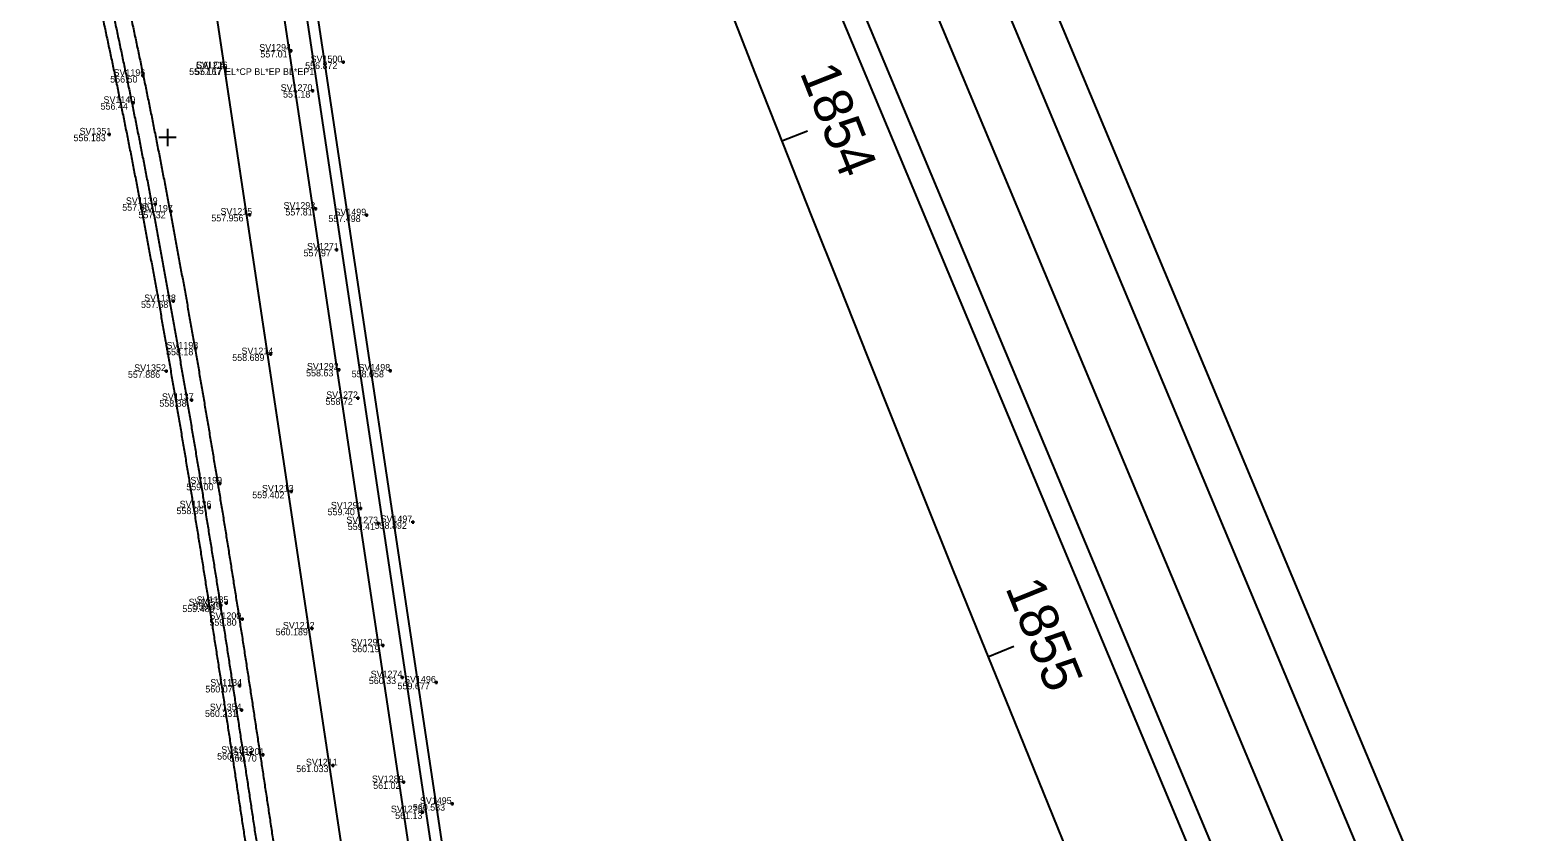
# Model space of a CAD drawing. Extents: x 6334 to 41599, y 9030 to 59113.
# Drawn here: x 21027.9 to 21299.4, y 34615.6 to 34759.9 of the extents above; entities that cross this region are included whole.
import ezdxf

# ---------------------------------------------------------------- set-up
doc = ezdxf.new("R2010")
doc.units = 0
for name, color, linetype in [('GE_X_CL_20', 7, 'Continuous'), ('GE_X_CL_50', 7, 'Continuous'), ('GK_Visualization', 7, 'Continuous'), ('PM_X_CL_Double_Solid', 7, 'Continuous'), ('PM_X_Lane_Line', 7, 'Continuous'), ('PV_X_EOP', 7, 'Continuous'), ('PV_X_Shoulder', 7, 'Continuous'), ('RD_X_GR_Lt', 7, 'Continuous'), ('RD_X_GR_Rt', 7, 'Continuous'), ('SV_X_Shot_Marker', 7, 'Continuous'), ('SV_X_Text_Comment', 7, 'Continuous'), ('SV_X_Text_Elevation', 7, 'Continuous'), ('SV_X_Text_Name', 7, 'Continuous')]:
    doc.layers.add(name, color=color, linetype=linetype)

msp = doc.modelspace()

# ---------------------------------------------------------------- linework, layer by layer
at = {"layer": 'GE_X_CL_20'}
msp.add_arc((24529.94, 36271.9), 3906.53, 186.21667, 209.21667, dxfattribs=at)
at = {"layer": 'GE_X_CL_50'}
for p, q in [((21163.23, 34739.98), (21167.88, 34741.81)), ((21200.36, 34647.12), (21205, 34649))]:
    msp.add_line(p, q, dxfattribs=at)
msp.add_arc((32581.78, 39251.96), 12277.67, 194.525, 202.716667, dxfattribs=at)
at = {"layer": 'GK_Visualization'}
for p, q in [((21051.3, 34829.99), (21084.27, 34610.45)), ((21051.3, 34829.99), (21084.27, 34610.45)), ((21182.19, 34784.02), (22003.54, 32822.13)), ((21054.16, 34740.61), (21051.04, 34740.61)), ((21052.6, 34742.17), (21052.6, 34739.05))]:
    msp.add_line(p, q, dxfattribs=at)
for centre, radius, start, end in [((32581.78, 39251.96), 12277.67, 194.525, 202.716667), ((32581.78, 39251.96), 12277.67, 194.525, 202.716667), ((24529.91, 36271.94), 3906.53, 186.21497, 209.2138), ((24529.91, 36271.94), 3906.53, 186.21497, 209.2138), ((24529.94, 36271.9), 3906.53, 186.21667, 209.21667), ((24529.94, 36271.9), 3906.53, 186.21667, 209.21667)]:
    msp.add_arc(centre, radius, start, end, dxfattribs=at)
msp.add_spline([(21035.84, 34805.21), (21036.52, 34802.59), (21037.19, 34799.97), (21037.85, 34797.35), (21038.5, 34794.73), (21039.15, 34792.11), (21039.79, 34789.48), (21040.42, 34786.85), (21041.04, 34784.22), (21041.66, 34781.59), (21042.28, 34778.96), (21042.88, 34776.33), (21043.48, 34773.69), (21044.08, 34771.05), (21044.66, 34768.42), (21045.24, 34765.78), (21045.82, 34763.13), (21046.39, 34760.49), (21046.95, 34757.85), (21047.51, 34755.21), (21048.06, 34752.56), (21048.61, 34749.91), (21049.15, 34747.26), (21049.69, 34744.62), (21050.22, 34741.97), (21050.75, 34739.31), (21051.27, 34736.66), (21051.78, 34734.01), (21052.29, 34731.36), (21052.8, 34728.7), (21053.3, 34726.05), (21053.8, 34723.39), (21054.3, 34720.73), (21054.78, 34718.07), (21055.27, 34715.42), (21055.75, 34712.76), (21056.23, 34710.1), (21056.7, 34707.43), (21057.17, 34704.77), (21057.64, 34702.11), (21058.1, 34699.45), (21058.56, 34696.78), (21059.01, 34694.12), (21059.46, 34691.46), (21059.91, 34688.79), (21060.36, 34686.12), (21060.8, 34683.46), (21061.24, 34680.79), (21061.68, 34678.12), (21062.11, 34675.46), (21062.55, 34672.79), (21062.98, 34670.12), (21063.4, 34667.45), (21063.83, 34664.78), (21064.25, 34662.11), (21064.67, 34659.44), (21065.09, 34656.77), (21065.51, 34654.1), (21065.92, 34651.43), (21066.34, 34648.76), (21066.75, 34646.09), (21067.16, 34643.42), (21067.57, 34640.75), (21067.98, 34638.08), (21068.38, 34635.4), (21068.79, 34632.73), (21069.2, 34630.06), (21069.6, 34627.39), (21070, 34624.72), (21070.41, 34622.04), (21070.81, 34619.37), (21071.21, 34616.7), (21071.61, 34614.03), (21072.01, 34611.35), (21072.42, 34608.68)], degree=3, dxfattribs=at)
at = {"layer": 'PM_X_CL_Double_Solid'}
msp.add_line((21061.45, 34762.43), (21084.27, 34610.45), dxfattribs=at)
at = {"layer": 'PM_X_Lane_Line'}
msp.add_line((21182.19, 34784.02), (22003.54, 32822.13), dxfattribs=at)
for start in [186.21667, 191.33607]:
    msp.add_arc((24529.94, 36271.9), 3906.53, start, 209.21667, dxfattribs=at)
at = {"layer": 'PV_X_EOP'}
for p, q in [((21063.16, 34831.77), (21096.14, 34612.23)), ((21193.26, 34788.66), (22014.61, 32826.77)), ((21171.12, 34779.39), (21992.47, 32817.5))]:
    msp.add_line(p, q, dxfattribs=at)
for centre, radius, start, end in [((24529.94, 36271.9), 3918.53, 191.33607, 209.21667), ((24531.79, 36272.61), 3896.49, 192.87045, 209.21252)]:
    msp.add_arc(centre, radius, start, end, dxfattribs=at)
msp.add_spline([(21035.84, 34805.21), (21036.52, 34802.59), (21037.19, 34799.97), (21037.85, 34797.35), (21038.5, 34794.73), (21039.15, 34792.11), (21039.79, 34789.48), (21040.42, 34786.85), (21041.04, 34784.22), (21041.66, 34781.59), (21042.28, 34778.96), (21042.88, 34776.33), (21043.48, 34773.69), (21044.08, 34771.05), (21044.66, 34768.42), (21045.24, 34765.78), (21045.82, 34763.13), (21046.39, 34760.49), (21046.95, 34757.85), (21047.51, 34755.21), (21048.06, 34752.56), (21048.61, 34749.91), (21049.15, 34747.26), (21049.69, 34744.62), (21050.22, 34741.97), (21050.75, 34739.31), (21051.27, 34736.66), (21051.78, 34734.01), (21052.29, 34731.36), (21052.8, 34728.7), (21053.3, 34726.05), (21053.8, 34723.39), (21054.3, 34720.73), (21054.78, 34718.07), (21055.27, 34715.42), (21055.75, 34712.76), (21056.23, 34710.1), (21056.7, 34707.43), (21057.17, 34704.77), (21057.64, 34702.11), (21058.1, 34699.45), (21058.56, 34696.78), (21059.01, 34694.12), (21059.46, 34691.46), (21059.91, 34688.79), (21060.36, 34686.12), (21060.8, 34683.46), (21061.24, 34680.79), (21061.68, 34678.12), (21062.11, 34675.46), (21062.55, 34672.79), (21062.98, 34670.12), (21063.4, 34667.45), (21063.83, 34664.78), (21064.25, 34662.11), (21064.67, 34659.44), (21065.09, 34656.77), (21065.51, 34654.1), (21065.92, 34651.43), (21066.34, 34648.76), (21066.75, 34646.09), (21067.16, 34643.42), (21067.57, 34640.75), (21067.98, 34638.08), (21068.38, 34635.4), (21068.79, 34632.73), (21069.2, 34630.06), (21069.6, 34627.39), (21070, 34624.72), (21070.41, 34622.04), (21070.81, 34619.37), (21071.21, 34616.7), (21071.61, 34614.03), (21072.01, 34611.35), (21072.42, 34608.68)], degree=3, dxfattribs=at)
at = {"layer": 'PV_X_Shoulder'}
for p, q in [((21067.12, 34832.37), (21100.09, 34612.83)), ((21200.64, 34791.75), (22021.99, 32829.86)), ((21167.43, 34777.85), (21988.78, 32815.95))]:
    msp.add_line(p, q, dxfattribs=at)
for radius, start in [(3926.53, 191.34141), (3890.53, 192.86631)]:
    msp.add_arc((24529.94, 36271.9), radius, start, 209.21667, dxfattribs=at)
msp.add_spline([(21032.94, 34804.46), (21033.61, 34801.85), (21034.28, 34799.24), (21034.94, 34796.62), (21035.59, 34794.01), (21036.23, 34791.39), (21036.87, 34788.77), (21037.5, 34786.15), (21038.12, 34783.53), (21038.74, 34780.91), (21039.35, 34778.28), (21039.96, 34775.66), (21040.56, 34773.03), (21041.15, 34770.4), (21041.73, 34767.77), (21042.31, 34765.13), (21042.89, 34762.5), (21043.46, 34759.86), (21044.02, 34757.23), (21044.57, 34754.59), (21045.13, 34751.95), (21045.67, 34749.31), (21046.21, 34746.67), (21046.75, 34744.02), (21047.28, 34741.38), (21047.8, 34738.73), (21048.32, 34736.09), (21048.84, 34733.44), (21049.35, 34730.79), (21049.85, 34728.14), (21050.36, 34725.49), (21050.85, 34722.84), (21051.35, 34720.19), (21051.83, 34717.53), (21052.32, 34714.88), (21052.8, 34712.22), (21053.27, 34709.57), (21053.75, 34706.91), (21054.22, 34704.25), (21054.68, 34701.6), (21055.14, 34698.94), (21055.6, 34696.28), (21056.05, 34693.62), (21056.51, 34690.96), (21056.95, 34688.29), (21057.4, 34685.63), (21057.84, 34682.97), (21058.28, 34680.3), (21058.72, 34677.64), (21059.15, 34674.98), (21059.58, 34672.31), (21060.01, 34669.65), (21060.44, 34666.98), (21060.87, 34664.31), (21061.29, 34661.65), (21061.71, 34658.98), (21062.13, 34656.31), (21062.54, 34653.64), (21062.96, 34650.97), (21063.37, 34648.3), (21063.78, 34645.63), (21064.19, 34642.96), (21064.6, 34640.29), (21065.01, 34637.62), (21065.42, 34634.95), (21065.82, 34632.28), (21066.23, 34629.61), (21066.63, 34626.94), (21067.04, 34624.27), (21067.44, 34621.6), (21067.84, 34618.92), (21068.24, 34616.25), (21068.65, 34613.58), (21069.05, 34610.91), (21069.45, 34608.23)], degree=3, dxfattribs=at)
at = {"layer": 'RD_X_GR_Lt'}
msp.add_line((21058.92, 34900.43), (21102.07, 34613.12), dxfattribs=at)
at = {"layer": 'RD_X_GR_Rt'}
msp.add_spline([(21031, 34803.96), (21031.68, 34801.35), (21032.34, 34798.74), (21033, 34796.14), (21033.65, 34793.53), (21034.29, 34790.92), (21034.93, 34788.3), (21035.56, 34785.69), (21036.18, 34783.07), (21036.79, 34780.45), (21037.4, 34777.83), (21038.01, 34775.21), (21038.61, 34772.59), (21039.2, 34769.96), (21039.78, 34767.33), (21040.36, 34764.71), (21040.93, 34762.08), (21041.5, 34759.44), (21042.06, 34756.81), (21042.62, 34754.18), (21043.17, 34751.54), (21043.71, 34748.91), (21044.25, 34746.27), (21044.79, 34743.63), (21045.32, 34740.99), (21045.84, 34738.35), (21046.36, 34735.7), (21046.87, 34733.06), (21047.38, 34730.41), (21047.89, 34727.77), (21048.39, 34725.12), (21048.89, 34722.47), (21049.38, 34719.82), (21049.87, 34717.17), (21050.35, 34714.52), (21050.83, 34711.87), (21051.31, 34709.22), (21051.78, 34706.56), (21052.25, 34703.91), (21052.71, 34701.25), (21053.17, 34698.6), (21053.63, 34695.94), (21054.08, 34693.28), (21054.53, 34690.62), (21054.98, 34687.96), (21055.43, 34685.3), (21055.87, 34682.64), (21056.31, 34679.98), (21056.74, 34677.32), (21057.18, 34674.66), (21057.61, 34671.99), (21058.04, 34669.33), (21058.47, 34666.66), (21058.89, 34664), (21059.31, 34661.33), (21059.73, 34658.67), (21060.15, 34656), (21060.57, 34653.33), (21060.98, 34650.67), (21061.4, 34648), (21061.81, 34645.33), (21062.22, 34642.66), (21062.63, 34639.99), (21063.03, 34637.32), (21063.44, 34634.65), (21063.85, 34631.98), (21064.25, 34629.31), (21064.66, 34626.64), (21065.06, 34623.97), (21065.46, 34621.3), (21065.86, 34618.63), (21066.27, 34615.95), (21066.67, 34613.28), (21067.07, 34610.61), (21067.47, 34607.94)], degree=3, dxfattribs=at)
at = {"layer": 'SV_X_Shot_Marker'}
for p, q in [((21075.14, 34756.22), (21074.54, 34756.22)), ((21074.84, 34756.52), (21074.84, 34755.92)), ((21084.56, 34754.15), (21083.96, 34754.15)), ((21084.26, 34754.45), (21084.26, 34753.85)), ((21048.48, 34751.7), (21047.88, 34751.7)), ((21048.18, 34752), (21048.18, 34751.4)), ((21063.27, 34753.07), (21062.67, 34753.07)), ((21063.27, 34753.07), (21062.67, 34753.07)), ((21063.27, 34753.07), (21062.67, 34753.07)), ((21062.97, 34753.37), (21062.97, 34752.77)), ((21062.97, 34753.37), (21062.97, 34752.77)), ((21062.97, 34753.37), (21062.97, 34752.77)), ((21079.02, 34748.99), (21078.42, 34748.99)), ((21078.72, 34749.29), (21078.72, 34748.69)), ((21046.7, 34746.82), (21046.1, 34746.82)), ((21046.4, 34747.12), (21046.4, 34746.52)), ((21042.41, 34741.14), (21041.81, 34741.14)), ((21042.11, 34741.44), (21042.11, 34740.84)), ((21050.69, 34728.62), (21050.09, 34728.62)), ((21050.39, 34728.92), (21050.39, 34728.32)), ((21053.49, 34727.27), (21052.89, 34727.27)), ((21053.19, 34727.57), (21053.19, 34726.97)), ((21067.69, 34726.7), (21067.09, 34726.7)), ((21067.39, 34727), (21067.39, 34726.4)), ((21079.55, 34727.77), (21078.95, 34727.77)), ((21079.25, 34728.07), (21079.25, 34727.47)), ((21088.73, 34726.6), (21088.13, 34726.6)), ((21088.43, 34726.9), (21088.43, 34726.3)), ((21083.32, 34720.4), (21082.72, 34720.4)), ((21083.02, 34720.7), (21083.02, 34720.1)), ((21053.93, 34711.13), (21053.33, 34711.13)), ((21053.63, 34711.43), (21053.63, 34710.83)), ((21057.96, 34702.6), (21057.36, 34702.6)), ((21057.66, 34702.9), (21057.66, 34702.3)), ((21071.45, 34701.58), (21070.85, 34701.58)), ((21071.15, 34701.88), (21071.15, 34701.28)), ((21052.65, 34698.55), (21052.05, 34698.55)), ((21052.35, 34698.85), (21052.35, 34698.25)), ((21083.74, 34698.8), (21083.14, 34698.8)), ((21083.44, 34699.1), (21083.44, 34698.5)), ((21093.02, 34698.62), (21092.42, 34698.62)), ((21092.72, 34698.92), (21092.72, 34698.32)), ((21086.87, 34693.98), (21086.87, 34693.38)), ((21057.25, 34693.34), (21056.65, 34693.34)), ((21056.95, 34693.64), (21056.95, 34693.04)), ((21087.17, 34693.68), (21086.57, 34693.68)), ((21062.3, 34678.3), (21061.7, 34678.3)), ((21062, 34678.6), (21062, 34678)), ((21075.17, 34676.85), (21074.57, 34676.85)), ((21074.87, 34677.15), (21074.87, 34676.55)), ((21060.39, 34674), (21059.79, 34674)), ((21060.09, 34674.3), (21060.09, 34673.7)), ((21087.64, 34673.8), (21087.04, 34673.8)), ((21087.34, 34674.1), (21087.34, 34673.5)), ((21090.82, 34671.14), (21090.22, 34671.14)), ((21090.52, 34671.44), (21090.52, 34670.84)), ((21097.09, 34671.35), (21096.49, 34671.35)), ((21096.79, 34671.65), (21096.79, 34671.05)), ((21062.48, 34656.36), (21061.88, 34656.36)), ((21062.18, 34656.66), (21062.18, 34656.06)), ((21063.44, 34656.79), (21062.84, 34656.79)), ((21063.14, 34657.09), (21063.14, 34656.49)), ((21066.35, 34653.91), (21065.75, 34653.91)), ((21066.05, 34654.21), (21066.05, 34653.61)), ((21078.91, 34652.18), (21078.31, 34652.18)), ((21078.61, 34652.48), (21078.61, 34651.88)), ((21091.68, 34649.14), (21091.08, 34649.14)), ((21091.38, 34649.44), (21091.38, 34648.84)), ((21065.57, 34642.19), (21065.57, 34641.59)), ((21095.16, 34643.4), (21094.56, 34643.4)), ((21094.86, 34643.7), (21094.86, 34643.1)), ((21101.29, 34642.46), (21100.69, 34642.46)), ((21100.99, 34642.76), (21100.99, 34642.16)), ((21065.87, 34641.89), (21065.27, 34641.89)), ((21066.25, 34637.48), (21065.65, 34637.48)), ((21065.95, 34637.78), (21065.95, 34637.18)), ((21067.88, 34629.8), (21067.28, 34629.8)), ((21067.58, 34630.1), (21067.58, 34629.5)), ((21070.06, 34629.45), (21069.46, 34629.45)), ((21069.76, 34629.75), (21069.76, 34629.15)), ((21082.66, 34627.55), (21082.06, 34627.55)), ((21082.36, 34627.85), (21082.36, 34627.25)), ((21095.43, 34624.53), (21094.83, 34624.53)), ((21095.13, 34624.83), (21095.13, 34624.23)), ((21104.14, 34620.61), (21103.54, 34620.61)), ((21103.84, 34620.91), (21103.84, 34620.31)), ((21098.84, 34619.12), (21098.24, 34619.12)), ((21098.54, 34619.42), (21098.54, 34618.82))]:
    msp.add_line(p, q, dxfattribs=at)

# ---------------------------------------------------------------- texts
at = {"layer": 'GE_X_CL_50'}
for s, rotation, p in [('1854', 291.5612, (21166.42, 34752.32)), ('1855', 292.0279, (21203.42, 34659.57))]:
    msp.add_text(s, height=7, rotation=rotation, dxfattribs=at).set_placement(p)
at = {"layer": 'SV_X_Text_Comment'}
msp.add_text('EL*CP BL*EP BL*EP1', height=1.2, dxfattribs=at).set_placement((21062.97, 34751.87))
at = {"layer": 'SV_X_Text_Elevation'}
for s, p in [('557.01', (21069.32, 34755.02)), ('556.872', (21077.39, 34752.95)), ('556.50', (21042.28, 34750.5)), ('557.167', (21056.5, 34751.87)), ('557.17', (21057.56, 34751.87)), ('557.17', (21057.56, 34751.87)), ('557.18', (21073.41, 34747.79)), ('556.44', (21040.55, 34745.62)), ('556.183', (21035.67, 34739.94)), ('557.05', (21044.45, 34727.42)), ('557.32', (21047.36, 34726.07)), ('557.956', (21060.49, 34725.5)), ('557.81', (21073.83, 34726.57)), ('557.498', (21081.58, 34725.4)), ('557.97', (21077.11, 34719.2)), ('557.68', (21047.83, 34709.93)), ('558.18', (21052.34, 34701.4)), ('558.689', (21064.26, 34700.38)), ('557.886', (21045.47, 34697.35)), ('558.63', (21077.56, 34697.6)), ('558.058', (21085.77, 34697.42)), ('558.38', (21051.13, 34692.14)), ('558.72', (21081.06, 34692.48)), ('559.00', (21055.98, 34677.1)), ('559.402', (21067.86, 34675.65)), ('558.95', (21054.22, 34672.8)), ('559.40', (21081.43, 34672.6)), ('559.41', (21085.06, 34669.94)), ('558.892', (21089.91, 34670.15)), ('559.489', (21055.27, 34655.16)), ('559.49', (21057.28, 34655.59)), ('559.80', (21060.14, 34652.71)), ('560.189', (21072.08, 34650.98)), ('560.19', (21085.88, 34647.94)), ('560.33', (21088.86, 34642.2)), ('559.677', (21094.03, 34641.26)), ('560.07', (21059.42, 34640.69)), ('560.231', (21059.35, 34636.28)), ('560.47', (21061.54, 34628.6)), ('560.70', (21063.76, 34628.25)), ('561.033', (21075.79, 34626.35)), ('561.02', (21089.64, 34623.33)), ('560.533', (21096.79, 34619.41)), ('561.13', (21093.6, 34617.92))]:
    msp.add_text(s, height=1.2, dxfattribs=at).set_placement(p)
at = {"layer": 'SV_X_Text_Name'}
for s, p in [('SV1294', (21069.13, 34756.22)), ('SV1216', (21057.71, 34753.07)), ('CALC4', (21057.73, 34753.07)), ('CALC8', (21057.75, 34753.07)), ('SV1500', (21078.37, 34754.15)), ('SV1196', (21042.88, 34751.7)), ('SV1270', (21072.98, 34748.99)), ('SV1140', (21041.08, 34746.82)), ('SV1351', (21036.76, 34741.14)), ('SV1139', (21045.11, 34728.62)), ('SV1197', (21047.85, 34727.27)), ('SV1215', (21062.14, 34726.7)), ('SV1293', (21073.49, 34727.77)), ('SV1499', (21082.67, 34726.6)), ('SV1271', (21077.73, 34720.4)), ('SV1138', (21048.39, 34711.13)), ('SV1198', (21052.42, 34702.6)), ('SV1214', (21065.93, 34701.58)), ('SV1352', (21046.6, 34698.55)), ('SV1292', (21077.71, 34698.8)), ('SV1498', (21086.99, 34698.62)), ('SV1137', (21051.6, 34693.34)), ('SV1272', (21081.18, 34693.68)), ('SV1199', (21056.72, 34678.3)), ('SV1213', (21069.61, 34676.85)), ('SV1136', (21054.79, 34674)), ('SV1291', (21082.02, 34673.8)), ('SV1273', (21084.81, 34671.14)), ('SV1497', (21090.97, 34671.35)), ('SV1353', (21056.41, 34656.36)), ('SV1135', (21057.85, 34656.79)), ('SV1200', (21060.17, 34653.91)), ('SV1212', (21073.38, 34652.18)), ('SV1290', (21085.6, 34649.14)), ('SV1134', (21060.31, 34641.89)), ('SV1274', (21089.19, 34643.4)), ('SV1496', (21095.21, 34642.46)), ('SV1354', (21060.22, 34637.48)), ('SV1133', (21062.28, 34629.8)), ('SV1201', (21064.34, 34629.45)), ('SV1211', (21077.53, 34627.55)), ('SV1289', (21089.41, 34624.53)), ('SV1495', (21098.06, 34620.61)), ('SV1275', (21092.83, 34619.12))]:
    msp.add_text(s, height=1.2, dxfattribs=at).set_placement(p)

doc.saveas('drawing.dxf')
